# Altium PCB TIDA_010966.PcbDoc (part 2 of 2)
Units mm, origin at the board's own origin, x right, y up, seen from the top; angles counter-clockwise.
Board outline 125.73 x 87.63 mm, 4 copper layers (Top Layer, Layer 1, Layer 2, Bottom Layer), stack 1.047 mm thick; 129 components, 41 nets, 410 pads, 452 vias.
Unrouted connection lines stored in the file: 3.
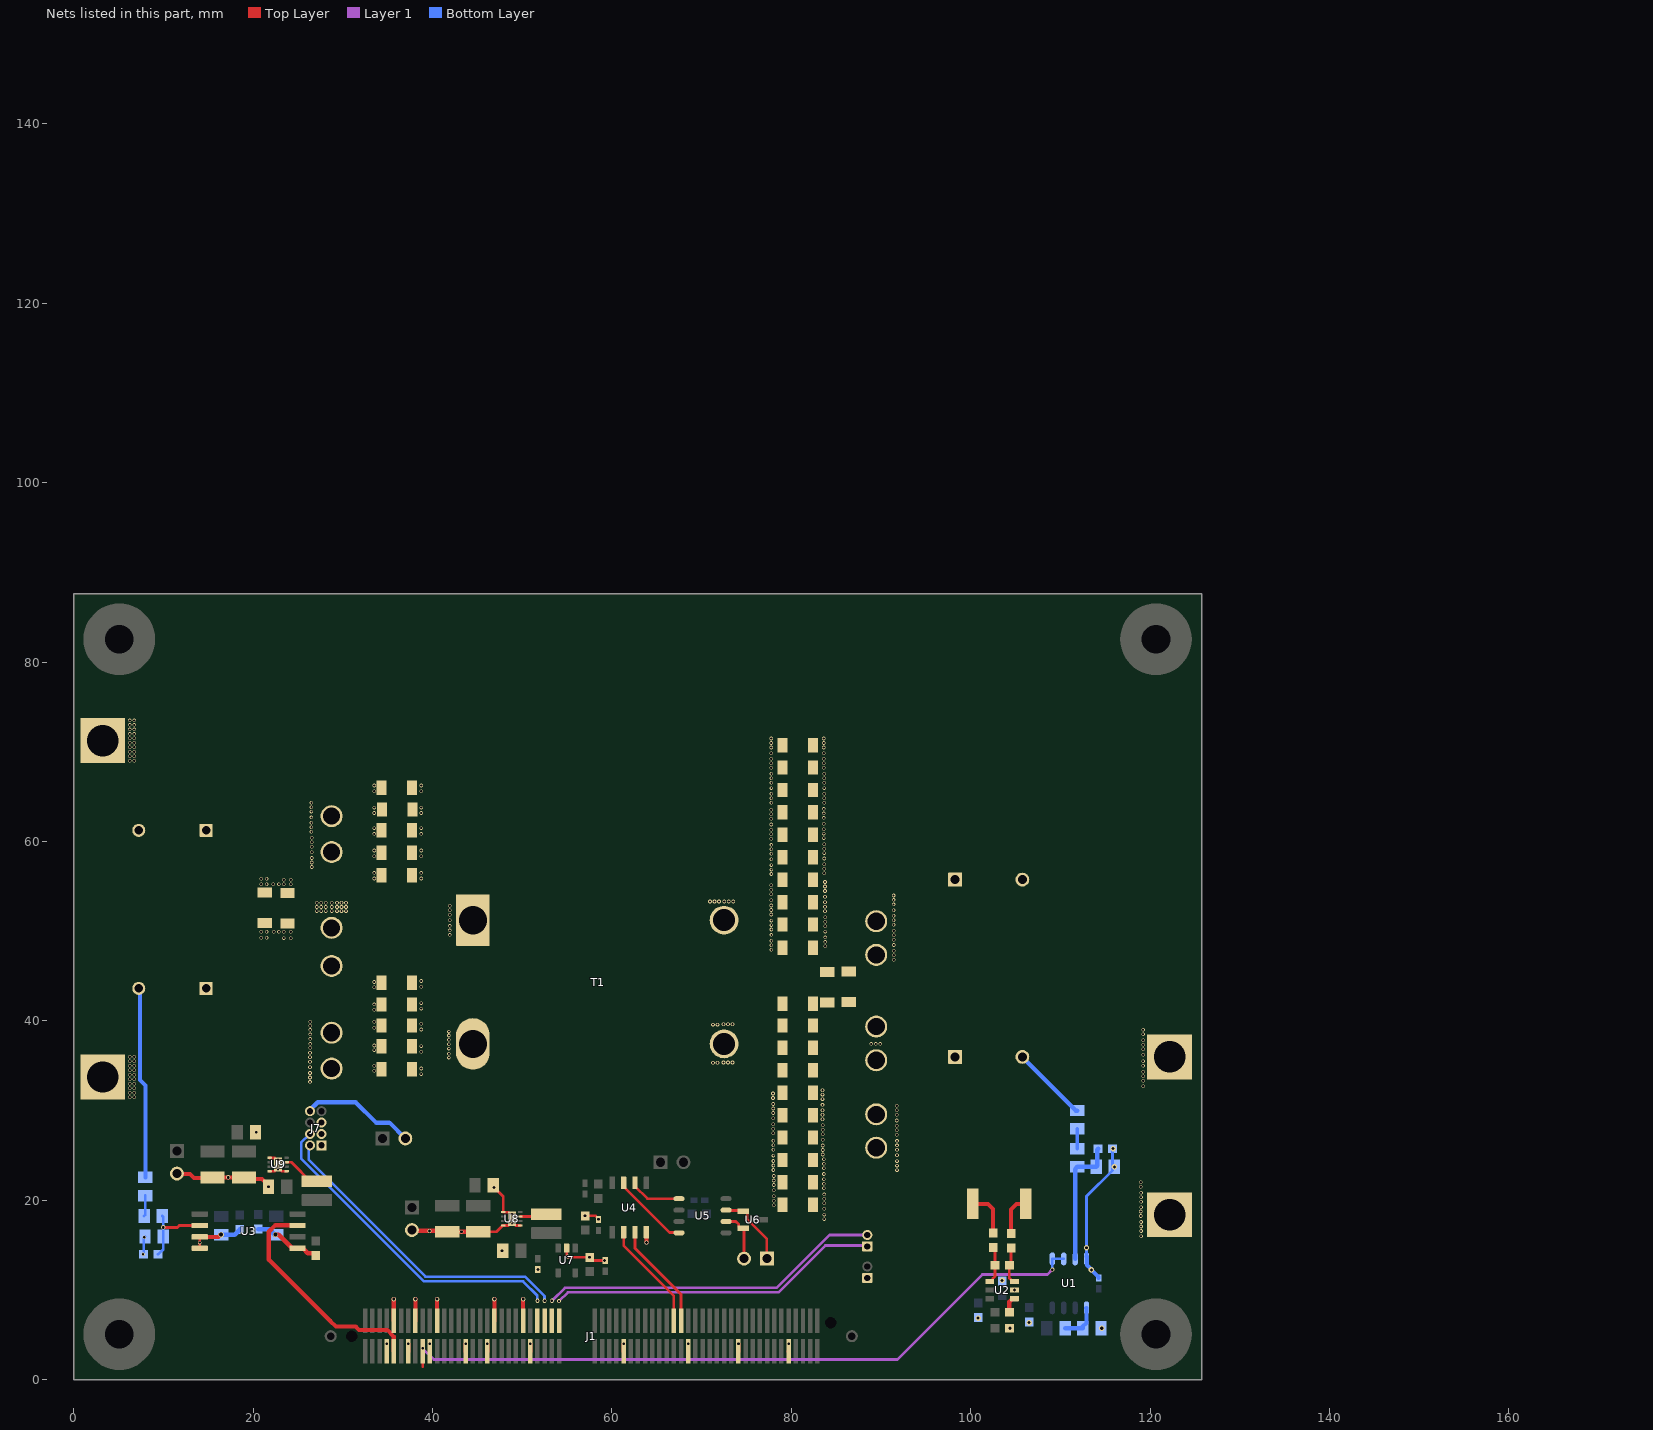
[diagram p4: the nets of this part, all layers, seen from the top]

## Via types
v1: diameter 0.4, hole 0.254, Top Layer to Bottom Layer, tented both sides, 371 vias
v2: diameter 0.5, hole 0.3, Top Layer to Bottom Layer, tented both sides, 31 vias
v3: diameter 0.61, hole 0.35, Top Layer to Bottom Layer, tented both sides, 14 vias
v4: diameter 0.43, hole 0.32, Top Layer to Bottom Layer, tented both sides, 12 vias
v5: diameter 0.45, hole 0.254, Top Layer to Bottom Layer, tented both sides, 5 vias
v6: diameter 0.45, hole 0.26, Top Layer to Bottom Layer, tented both sides, 4 vias
v7: diameter 0.61, hole 0.45, Top Layer to Bottom Layer, tented both sides, 4 vias
v8: diameter 0.5, hole 0.2, Top Layer to Bottom Layer, 4 vias
v9: diameter 0.45, hole 0.33, Top Layer to Bottom Layer, tented both sides, 3 vias
v10: diameter 0.61, hole 0.3, Top Layer to Bottom Layer, tented both sides, 3 vias
v11: diameter 0.45, hole 0.25, Top Layer to Bottom Layer, tented both sides, 1 vias

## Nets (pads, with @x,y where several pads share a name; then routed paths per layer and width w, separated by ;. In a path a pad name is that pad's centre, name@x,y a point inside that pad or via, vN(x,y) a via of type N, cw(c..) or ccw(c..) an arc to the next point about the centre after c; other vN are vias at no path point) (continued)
GND_pri: C5.1 C6.2 C7.2 C8.1 C9.1 C14.2 C15.2 C22.2 C24.2 C26.2 C28.2 C30.2 C64.1 C67.1 C70.2 C74.2 GND_pri2.1 GND_pri.1 J5.2 J7.1 pad.2@3.228,33.75 R11.1 U3.3 U3.4 U9.1 U9.4 U9.5 U9.9@22.78,24 | length 22.7
  Top Layer w0.3: U3.4@14.05,14.659 U3.3@14.05,15.929 ; U9.4@21.83,23.25 22.38,23.25 22.58,23.45 22.98,23.45 23.18,23.25 U9.5@23.73,23.25 ; U9.1@21.83,24.75 21.855,24.725 22.405,24.725 22.58,24.55 v8(22.78,24.55) ; U9.9@22.68,23.55 22.78,23.65 U9.9@22.78,24
  Top Layer w0.45: J5.2@11.5,22.98 11.525,22.955 12.95,22.955 13.416,22.489 15.419,22.489 C67.1@15.48,22.55 v2(17.23,22.55) C64.1@18.98,22.55 19.156,22.374 21.005,22.374 21.714,21.665 v10(21.714,21.5) ; U3.3@14.05,15.929 16.15,15.929 16.389,16.168 v7(16.432,16.168)
  Bottom Layer w0.3: C6.2@7.804,13.995 7.804,15.821 R11.1@7.947,15.964
  Bottom Layer w0.5: v7(16.432,16.168) 17.935,16.168 18.5,16.733 C7.2@18.5,16.758
  other v1: 7.729,13.995 14.05,15.294 7.863,15.88 6.25,31.5 6.75,31.5 6.25,32 6.75,32 6.25,32.5 6.75,32.5 6.25,33 6.75,33 26.34,33.2 6.25,33.5 6.75,33.5 26.34,33.7 6.25,34 6.75,34 26.34,34.2 33.5,34.457 6.25,34.5 6.75,34.5 26.34,34.85 6.25,35 6.75,35 33.5,35 26.34,35.45 6.25,35.5 6.75,35.5 26.34,35.95 6.25,36 6.75,36 26.34,36.45 33.5,36.75 26.357,37 33.5,37.266 26.355,37.439 26.355,38 26.355,38.5 26.355,39 33.5,39.25 26.355,39.459 26.357,39.9 33.5,39.9 33.5,41.25 33.5,41.841 33.5,43.75 33.5,44.339 24.208,49.227 23.427,49.239 21.5,49.275 20.901,49.289 20.901,49.95 21.5,49.95 22.301,49.95 22.877,49.95 23.427,49.95 24.208,49.95
  other v2: 20.35,27.589
  other v8: 22.78,23.45
GND_sec: C1.2 C2.2 C3.2 C10.1 C16.2 C17.1 C18.2 C19.1 C20.2 C31.1 C32.1 C34.2 C36.2 C40.2 C42.2 C44.2 C46.2 C50.2 C52.2 C54.2 C56.2 C57.1 C58.1 C59.2 C62.1 C63.2 C66.1 C68.2 C69.2 C71.2 C72.2 C73.2 GND_sec2.1 GND_sec.1 J1.7 J1.10 J1.13 J1.16 J1.19 J1.22 J1.29 J1.35 J1.38 J1.46 J1.47 J1.65 J1.83 J1.97 J1.111 J4.2 J7.3 J7.5 J9.1 R4.1 R8.1 R10.1 R12.1 U1.4 U2.2 U3.5 U4.4 U7.2 U8.1 U8.4 U8.5 U8.9@48.85,17.952 | length 75.6
  Top Layer w0.3: C62.1@45.1,16.502 47.125,16.502 47.825,17.202 U8.4@47.9,17.202 48.45,17.202 48.65,17.402 v8(48.85,17.402) ; C69.2@46.766,21.702 46.766,21.537 47.9,20.403 U8.1@47.9,18.702 47.925,18.677 48.475,18.677 48.65,18.502 v8(48.85,18.502) ; U8.9@48.85,17.952 48.85,17.602 49.25,17.202 U8.5@49.8,17.202 ; U7.2@54.95,14.677 54.95,13.828 55.126,13.652 v4(57.5,13.652) 57.5,13.627 57.825,13.302 C71.2@59.25,13.302 ; v4(57,18.278) 58.172,18.278 58.5,17.95 C31.1@58.5,17.85
  Top Layer w0.45: J1.7@34.9,3.157 v2(34.9,4) ; v2(35.675,9) 35.675,6.582 J1.10@35.7,6.557 ; J1.13@37.3,3.157 v2(37.3,4) ; J1.16@38.1,6.557 v2(38.1,9) ; J1.19@39.7,3.157 v2(39.7,4) ; J1.22@40.5,6.557 v2(40.5,9) ; J1.29@43.7,3.157 v2(43.7,4) ; J1.35@46.1,3.157 v2(46.1,4) ; J1.38@46.9,6.557 v2(46.9,9) ; J1.46@50.1,6.557 v2(50.1,9) ; J1.47@50.9,3.157 v2(50.9,4) ; J1.65@61.3,3.157 v2(61.3,4) ; v4(63.84,15.303) U4.4@63.84,16.453 ; v2(68.498,4) 68.498,3.159 J1.83@68.5,3.157 ; J1.97@74.1,3.157 v2(74.1,4) ; J1.111@79.7,3.157 79.714,3.171 v2(79.714,4) ; R10.1@100.237,19.6 101.914,19.6 102.494,19.02 R4.1@102.494,16.35
  Top Layer w0.5: v7(22.492,16.183) 22.513,16.162 22.847,16.162 24.35,14.659 U3.5@24.95,14.659 25.55,14.659 26.1,14.109 26.755,14.109 26.98,13.884 C19.1@26.98,13.859 ; J4.2@37.7,16.682 37.79,16.592 41.551,16.592 C66.1@41.641,16.502 C62.1@45.1,16.502
  Bottom Layer w0.3: U1.4@112.905,13.752 112.905,20.458 115.8,23.353 C3.2@115.8,25.766
  Bottom Layer w0.45: U1.4@112.905,13.752 112.934,13.723 112.934,12.766 114.25,11.45 C20.2@114.25,11.35
  Bottom Layer w0.5: C17.1@20.575,16.799 21.794,16.799 22.41,16.183 v7(22.492,16.183) C18.2@22.575,16.183
  other v1: 83.662,17.914 83.662,18.414 83.662,19.064 83.662,19.664 83.662,20.164 83.662,20.664 83.633,21.339 83.633,21.839 83.633,22.339 83.633,22.939 91.779,23.377 83.633,23.589 91.779,23.877 83.633,24.089 91.779,24.377 83.633,24.589 91.779,25.027 83.498,25.114 83.498,25.614 91.779,25.627 83.498,26.114 91.779,26.127 91.779,26.627 83.498,26.764 91.75,27.302 83.498,27.364 91.75,27.802 83.498,27.864 91.75,28.302 83.498,28.364 91.75,28.902 83.469,29.039 83.469,29.539 91.75,29.552 83.469,30.039 91.75,30.052 91.75,30.552 83.469,30.639 83.469,31.289 83.469,31.789 83.469,32.289
  other v3: 104.369,5.75 114.6,5.75 106.511,6.375 100.815,6.877 103.494,11.077 113.45,12.25 116.016,23.734 115.875,25.766
  other v4: 104.869,10 51.75,12.282 59.191,13.302 55.038,13.74 47.75,14.376 43.241,16.502 39.67,16.592 58.5,17.9 46.85,21.453
  other v10: 112.905,14.7
NetC3_1: C3.1 R2.1 R12.2 U1.3 | length 14.6
  Bottom Layer w0.5: U1.3@111.635,13.475 111.635,23.494 R2.1@111.875,23.734 R12.2@113.984,23.734 114.092,23.842 114.092,25.658 C3.1@114.2,25.766
NetC4_1: C4.1 R3.2 U2.3 | length 4.2
  Top Layer w0.3: R3.2@104.494,14.7 104.494,12.95 C4.1@104.294,12.75 104.294,11.325 104.669,10.95 U2.3@104.869,10.95
NetC4_2: C4.2 R4.2 U2.4 | length 4.2
  Top Layer w0.3: U2.4@102.119,10.95 102.319,10.95 102.469,11.1 102.469,11.3 102.694,11.525 C4.2@102.694,12.75 102.694,14.55 R4.2@102.494,14.75
NetC6_1: C6.1 R6.1 R11.2 U3.2 | length 8.7
  Top Layer w0.3: v2(9.979,16.98) 11.545,16.98 11.764,17.199 U3.2@14.05,17.199
  Bottom Layer w0.3: C6.1@9.404,13.995 9.429,13.995 9.979,14.545 R11.2@9.979,15.964 v2(9.979,16.98) 9.979,18.15 R6.1@9.875,18.255
NetC21_2: C21.2 C22.1 C23.2 C24.1 C25.2 C26.1 C27.2 C28.1 C29.2 C30.1 T1.2
  other v1: 38.75,34.079 38.75,34.701 41.827,35.917 41.826,36.355 38.75,36.551 41.826,36.917 38.75,37.201 41.826,37.417 41.826,37.917 41.826,38.376 41.827,38.817 38.75,39.051 38.75,39.701 38.75,41.378 38.75,41.99 38.75,43.801 38.75,44.451 38.75,55.877 38.75,56.5 38.75,58.35 38.75,59 38.75,60.85 38.75,61.5 38.75,63.177 38.75,63.789 38.75,65.6 38.75,66.25
NetC33_2: C33.2 C34.1 C35.2 C36.1 C39.2 C40.1 C41.2 C42.1 C43.2 C44.1 C45.2 C46.1 C49.2 C50.1 C51.2 C52.1 C53.2 C54.1 C55.2 C56.1 T1.4
  other v1: 78.029,19.464 78.029,19.964 78.029,20.464 78.029,21.114 78.029,21.714 78.029,22.214 78.029,22.714 78,23.389 78,23.889 78,24.389 78,24.989 78,25.639 78,26.139 78,26.639 77.988,27.489 77.988,27.989 77.988,28.489 77.988,29.139 77.988,29.739 77.988,30.239 77.988,30.739 77.959,31.414 77.959,31.914 77.779,47.941 77.779,48.441 77.779,48.941 77.779,49.591 77.779,50.191 77.779,50.691 77.779,51.191 77.75,51.866 77.75,52.366 77.75,52.866 70.931,53.321 71.431,53.321 71.931,53.321 72.525,53.321 73.025,53.321 73.525,53.321 77.75,53.466 77.75,54.116 77.75,54.616 77.75,55.116 77.779,56.377 77.779,56.877 77.779,57.377 77.779,58.027 77.779,58.627 77.779,59.127 77.779,59.627 77.75,60.302 77.75,60.802 77.75,61.302 77.75,61.902 77.75,62.552 77.75,63.052 77.75,63.552 77.779,64.314 77.779,64.814 77.779,65.314 77.779,65.964 77.779,66.564 77.779,67.064 77.779,67.564 77.75,68.239 77.75,68.739 77.75,69.239 77.75,69.839 77.75,70.489 77.75,70.989 77.75,71.489
NetJ1_80: J1.80 U4.2 | length 12.2
  Top Layer w0.3: U4.2@61.3,16.453 61.3,14.95 66.9,9.35 J1.80@66.9,6.557
NetJ1_82: J1.82 U4.3 | length 12
  Top Layer w0.3: U4.3@62.57,16.453 62.57,14.66 67.7,9.53 J1.82@67.7,6.557
NetJ3_1: J3.1 U5.7 U6.1 | length 8.5
  Top Layer w0.3: U5.7@72.725,18.913 72.773,18.865 74.584,18.865 U6.1@74.65,18.8 74.949,18.8 75.099,18.65 75.099,17.866 77.27,15.695 J3.1@77.27,13.5
NetJ3_2: J3.2 U5.6 U6.2 | length 5.8
  Top Layer w0.3: U5.6@72.725,17.643 73.8,17.643 74.15,17.293 74.15,17.05 74.3,16.9 U6.2@74.65,16.9 74.73,16.82 J3.2@74.73,13.5
NetL1_1: L1.1 U8.7 | length 3
  Top Layer w0.3: U8.7@49.8,18.202 52.45,18.202 L1.1@52.7,18.452
NetL2_1: L2.1 U9.7 | length 5.9
  Top Layer w0.3: U9.7@23.73,24.25 24.278,24.25 26.58,21.948 L2.1@28.65,21.948
NetR1_1: R1.1 R2.2 | length 2.2
  Bottom Layer w0.381: R2.2@111.875,25.766 R1.1@111.875,27.984
NetR5_1: R5.1 R6.2 | length 2.3
  Bottom Layer w0.3: R6.2@7.843,18.255 7.979,18.391 R5.1@7.979,20.532
NetR7_1: R7.1 R8.2 U1.5 | length 4.5
  Bottom Layer w0.45: R8.2@112.484,5.75 112.484,5.915 112.905,6.336 U1.5@112.905,8.025 U1.5@112.876,7.996
  Bottom Layer w0.5: R7.1@110.516,5.75 R8.2@112.484,5.75
NetR9_1: R9.1 U2.1 | length 1.9
  Top Layer w0.5: R9.1@104.294,7.5 104.294,8.675 104.669,9.05 U2.1@104.869,9.05
NetU4_6: U4.6 U5.1 | length 5.9
  Top Layer w0.3: U4.6@62.57,21.953 62.57,21.553 63.94,20.183 U5.1@67.475,20.183
NetU4_7: U4.7 U5.4 | length 8.7
  Top Layer w0.3: U4.7@61.3,21.953 61.3,21.553 66.432,16.421 67.427,16.421 U5.4@67.475,16.373
Q1_G: J1.50 J7.4 | length 36.4
  Layer 1 w0.3: J7.4@26.332,27.402 J7.4@26.349,27.402 ; v6@51.671,8.836 v6(51.7,8.807)
  Bottom Layer w0.3: J7.4@26.332,27.402 25.359,26.429 25.359,24.657 39.039,10.977 50.1,10.977 51.671,9.406 v6@51.671,8.836
Q2_G: J1.52 J7.2 | length 34.8
  Layer 1 w0.3: J7.2@26.192,25.976 J7.2@26.349,26.132 ; v6@52.471,8.836 v6(52.5,8.807)
  Bottom Layer w0.3: J7.2@26.192,25.976 26.192,24.531 39.223,11.5 50.284,11.5 52.471,9.313 v6@52.471,8.836
Q3_G: J1.54 J8.2 | length 38.2
  Layer 1 w0.3: v6(53.3,8.807) 54.743,10.25 78.36,10.25 84.247,16.137 J8.2@88.464,16.137
Q4_G: J1.56 J8.1 | length 37
  Layer 1 w0.3: v6(54.1,8.765) 55.085,9.75 78.567,9.75 83.784,14.966 88.365,14.966 J8.1@88.464,14.867
SW_pri: J6.2 J7.8 SW_pri2.1 SW_pri.1 T1.1 | length 12.8
  Bottom Layer w0.5: J7.8@26.349,29.942 26.349,30.101 27.201,30.952 31.42,30.952 33.7,28.672 35.2,28.672 J6.2@36.97,26.903
  other v1: 41.933,49.591 41.933,50.091 41.933,50.591 41.933,51.241 41.933,51.841 27.101,52.25 27.601,52.25 28.101,52.25 28.751,52.25 29.351,52.25 29.851,52.25 30.351,52.25 41.933,52.341 27.101,52.7 27.601,52.7 28.101,52.7 28.751,52.7 29.351,52.7 29.851,52.7 30.351,52.7 41.933,52.841 27.101,53.165 27.601,53.165 28.101,53.165 28.751,53.165 29.351,53.165 29.851,53.165 30.351,53.165
SW_sec: SW_sec2.1 SW_sec.1 T1.3
  other v1: 71.265,35.34 71.765,35.34 72.44,35.369 72.94,35.369 73.44,35.369 88.92,37.439 89.42,37.439 89.92,37.439 71.265,39.598 71.765,39.598 72.44,39.627 72.94,39.627 73.44,39.627
Vbattery_n: pad.2@122.174,18.4 R3.1 R10.2 | length 4.6
  Top Layer w0.45: R3.1@104.494,16.3 104.494,18.987 105.108,19.6 R10.2@106.137,19.6
  other v1: 118.988,15.985 118.988,16.585 118.988,17.085 118.988,17.585 118.959,18.26 118.959,18.76 118.988,19.235 118.988,19.835 118.988,20.335 118.988,20.835 118.959,21.51 118.959,22.01
Vbattery_p: C33.1 C35.1 C39.1 C41.1 C43.1 C45.1 C49.1 C51.1 C53.1 C55.1 C57.2 C58.2 C59.1 C68.1 pad.2@122.174,36 R1.2 Vbattery_p2.1 Vbattery_p.1 | length 8.6
  Bottom Layer w0.5: C58.2@105.75,36 105.75,35.976 111.71,30.016 R1.2@111.875,30.016
  other v1: 119.238,32.735 119.238,33.335 119.238,33.835 119.238,34.335 119.209,35.01 119.209,35.51 119.238,36.235 119.238,36.835 119.238,37.335 119.238,37.835 119.209,38.51 119.209,39.01 91.429,46.814 91.429,47.314 91.429,47.814 83.779,48.314 91.429,48.464 83.779,48.814 91.429,49.064 83.779,49.314 91.429,49.564 83.779,49.964 91.429,50.064 83.779,50.564 91.4,50.739 83.779,51.064 91.4,51.239 83.779,51.564 91.4,51.739 83.75,52.239 91.4,52.339 83.75,52.739 91.4,52.989 83.75,53.239 91.4,53.489 83.75,53.839 91.4,53.989 83.75,54.489 83.75,54.989 83.75,55.489 83.654,56.461 83.654,56.961 83.654,57.461 83.654,58.111 83.654,58.711 83.654,59.211 83.654,59.711 83.625,60.386 83.625,60.886 83.625,61.386 83.625,61.986 83.625,62.636 83.625,63.136 83.625,63.636 83.654,64.314 83.654,64.814 83.654,65.314 83.654,65.964 83.654,66.564 83.654,67.064 83.654,67.564 83.625,68.239 83.625,68.739 83.625,69.239 83.625,69.839 83.625,70.489 83.625,70.989 83.625,71.489
Vbattery_sen: J1.17 U1.1 U1.2 | length 79
  Top Layer w0.3: 38.9,1.452 J1.17@38.9,3.157
  Layer 1 w0.3: v5(38.9,3.5) 40.143,2.257 91.821,2.257 101.296,11.732 108.544,11.732 v11(109.088,12.275)
  Bottom Layer w0.3: v11(109.088,12.275) 109.095,12.282 U1.1@109.095,13.475 U1.2@110.365,13.475
Vbus_p: C5.2 C9.2 C14.1 C15.1 C21.1 C23.1 C25.1 C27.1 C29.1 pad.2@3.228,71.25 R5.2 Vbus_p2.1 Vbus_p.1 | length 21.4
  Bottom Layer w0.45: C9.2@7.25,43.627 7.375,43.502 7.375,33.405 7.979,32.801 R5.2@7.979,22.564
  other v1: 20.901,55.25 21.5,55.25 22.228,55.25 22.877,55.25 23.427,55.25 24.208,55.25 23.427,55.734 24.2,55.734 20.901,55.85 21.5,55.85 33.5,55.877 33.5,56.5 26.529,57.164 26.529,57.664 26.529,58.164 33.5,58.35 26.529,58.814 33.5,59 26.529,59.414 26.529,59.914 26.529,60.414 33.5,60.85 26.5,61.089 33.5,61.5 26.5,61.589 26.5,62.089 26.5,62.689 33.5,63.177 26.5,63.339 33.5,63.789 26.5,63.839 26.5,64.339 33.5,65.6 33.5,66.25 6.25,69 6.75,69 6.25,69.5 6.75,69.5 6.25,70 6.75,70 6.25,70.5 6.75,70.5 6.25,71 6.75,71 6.25,71.5 6.75,71.5 6.25,72 6.75,72 6.25,72.5 6.75,72.5 6.25,73 6.75,73 6.25,73.5 6.75,73.5
Vbus_sense: J1.9 U3.7 | length 25.8
  Top Layer w0.45: 28.58,6.557 29.22,5.917 31.439,5.917 31.824,5.532 34.968,5.532 35.675,4.825 35.675,3.182 J1.9@35.7,3.157
  Top Layer w0.5: U3.7@24.95,17.199 22.441,17.199 21.738,16.496 21.738,13.4 28.58,6.557
pads on no net: H1.1 H2.1 H3.1 H4.1 H5.0 H6.0 H7.0 H8.0 H9.0 H10.0 H11.0 H12.0 J1.1 J1.2 J1.3 J1.4 J1.5 J1.6 J1.8 J1.12 J1.14 J1.18 J1.20 J1.21 J1.23 J1.24 J1.25 J1.26 J1.27 J1.28 J1.30 J1.31 J1.32 J1.33 J1.34 J1.36 J1.37 J1.39 J1.40 J1.41 J1.42 J1.43 J1.44 J1.45 J1.49 J1.51 J1.53 J1.55 J1.57 J1.58 J1.59 J1.60 J1.61 J1.62 J1.63 J1.64 J1.66 J1.67 J1.68 J1.69 J1.70 J1.71 J1.72 J1.73 J1.74 J1.75 J1.76 J1.77 J1.78 J1.79 J1.81 J1.85 J1.86 J1.87 J1.88 J1.89 J1.90 J1.91 J1.92 J1.93 J1.94 J1.95 J1.96 J1.99 J1.100 J1.101 J1.102 J1.103 J1.104 J1.105 J1.106 J1.107 J1.108 J1.109 J1.110 J1.113 J1.114 J1.115 J1.116 J1.117 J1.118 J1.119 J1.120 J1.181 J1.182 J1.185 J1.186 U5.5 U7.4 U8.8 U8.9@48.85,17.502 U8.9@48.85,18.402 U9.8 U9.9@22.78,23.55 U9.9@22.78,24.45

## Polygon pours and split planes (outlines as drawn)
NetC33_2 on Top Layer "TOP_LAYER_NETC33_2_P020" (solid, remove dead copper, pour order 20): 72,76.5 70.25,74.75 70.25,49.795 76.241,43.804 76.241,20.407 77.924,18.723 79.197,18.723 80,19.527 80,75.5 79,76.5
Vbattery_p on Top Layer "TOP_LAYER_VBATTERY_P_P021" (solid, remove dead copper, pour order 21): 84,76.5 82,74.5 82,46.25 83.407,44.843 90.168,44.843 91.939,46.615 91.939,68.25 102.75,68.25 104,67 104,33.8 106.3,31.5 111.25,31.5 112.5,32.75 112.5,74.25 110.25,76.5
GND_sec on Top Layer "TOP_LAYER_GND_SEC_P005" (solid, remove dead copper, pour order 5): 100.15,59 100.75,58.4 100.75,18.75 99.25,17.25 83.864,17.25 82.114,19 82.114,42.614 82.5,43 91,43 94.687,46.687 94.687,58.418 95.269,59
NetC21_2 on Top Layer "TOP_LAYER_NETC21_2_P017" (solid, remove dead copper, pour order 17): 37.5,74.5 37,74 37,32.792 38.864,30.927 47.364,30.927 48.76,32.323 48.76,39.834 46.664,41.929 42.871,41.929 41.5,43.3 41.5,74.075 41.075,74.5
Vbattery_p on Top Layer "TOP_LAYER_VBATTERY_P_P009" (solid, remove dead copper, pour order 9): 107.107,39.25 106.459,38.308 106.459,32.352 107.311,31.5 124.455,31.5 125.083,32.128 125.083,38.575 124.504,39.25
Vbattery_n on Top Layer "TOP_LAYER_VBATTERY_N_P008" (solid, remove dead copper, pour order 8): 106.511,22.718 105.914,21.849 105.914,16.327 106.766,15.475 124.705,15.475 125.175,15.945 125.175,22.054 124.606,22.718
GND_pri on Top Layer "TOP_LAYER_GND_PRI_P007" (solid, remove dead copper, pour order 7): 0.647,36.66 0.647,31 15,31 15,34 12.34,36.66
GND_pri on Top Layer "TOP_LAYER_GND_PRI_P001" (solid, remove dead copper, pour order 1): 12.491,64.069 11.916,63.494 11.916,34 14.916,31 33.333,31 35.148,32.815 35.148,49.95 34.098,51 18.615,51 17.25,52.365 17.25,63.5 16.681,64.069
Vbus_p on Top Layer "TOP_LAYER_VBUS_P_P000" (solid, remove dead copper, pour order 0): 9,40.75 8,39.75 2,39.75 0.647,41.103 0.647,73.897 1.25,74.5 33.01,74.5 35.25,72.26 35.25,55.877 33.623,54.25 20.351,54.25 20.351,66.25 19.351,67.25 11,67.25 9,65.25
SW_sec on Layer 2 "LAYER_2_SW_SEC_P025" (solid, remove dead copper, pour order 25): 72.229,43.5 70.3,41.571 70.3,34.824 72.474,32.65 92.425,32.65 93.285,33.51 93.285,41.268 91.053,43.5
SW_pri on Layer 2 "LAYER_2_SW_PRI_P016" (solid, remove dead copper, pour order 16): 27.637,55.066 26.085,53.515 26.085,45.926 27.673,44.339 31.472,44.339 34.415,47.281 46.53,47.281 48,48.752 48,53.25 46.25,55
GND_sec on Layer 2 "LAYER_2_GND_SEC_P013" (solid, remove dead copper, pour order 13): 71.588,29.25 24.73,29.25 19.429,23.949 19.429,3.106 21.559,0.976 115.64,0.976 117.654,2.99 117.654,27.196 115.85,29 108.137,29 105.542,26.405 105.542,17.718 104.847,17.024 76.379,17.024 75.5,17.902 75.5,25.338
NetC33_2 on Layer 1 "LAYER_1_NETC33_2_P019" (solid, remove dead copper, pour order 19): 72,76.5 70.25,74.75 70.25,49.795 76.241,43.804 76.241,20.407 77.924,18.723 79.197,18.723 80,19.527 80,75.5 79,76.5
Vbattery_n on Layer 1 "LAYER_1_VBATTERY_N_P026" (solid, remove dead copper, pour order 26): 106.511,22.718 105.914,21.849 105.914,16.327 106.766,15.475 124.705,15.475 125.175,15.945 125.175,22.054 124.606,22.718
GND_sec on Layer 1 "LAYER_1_GND_SEC_P023" (solid, remove dead copper, pour order 23): 100.15,59 100.75,58.4 100.75,18.75 99.25,17.25 83.864,17.25 82.114,19 82.114,42.614 82.5,43 91,43 94.687,46.687 94.687,58.418 95.269,59
Vbattery_p on Layer 1 "LAYER_1_VBATTERY_P_P022" (solid, remove dead copper, pour order 22): 107.107,39.25 106.459,38.308 106.459,32.352 107.311,31.5 124.455,31.5 125.083,32.128 125.083,38.575 124.504,39.25
Vbattery_p on Layer 1 "LAYER_1_VBATTERY_P_P004" (solid, remove dead copper, pour order 4): 84,76.5 82,74.5 82,46.25 83.407,44.843 90.168,44.843 91.939,46.615 91.939,68.25 102.75,68.25 104,67 104,33.8 106.3,31.5 111.25,31.5 112.5,32.75 112.5,74.25 110.25,76.5
NetC21_2 on Layer 1 "LAYER_1_NETC21_2_P018" (solid, remove dead copper, pour order 18): 37.5,74.5 37,74 37,32.792 38.864,30.927 47.364,30.927 48.76,32.323 48.76,39.834 46.664,41.929 42.871,41.929 41.5,43.3 41.5,74.075 41.075,74.5
GND_pri on Layer 1 "LAYER_1_GND_PRI_P006" (solid, remove dead copper, pour order 6): 0.647,36.66 0.647,31 15,31 15,34 12.34,36.66
GND_pri on Layer 1 "LAYER_1_GND_PRI_P003" (solid, remove dead copper, pour order 3): 12.491,64.069 11.916,63.494 11.916,34 14.916,31 33.333,31 35.148,32.815 35.148,49.95 34.098,51 18.615,51 17.25,52.365 17.25,63.5 16.681,64.069
Vbus_p on Layer 1 "LAYER_1_VBUS_P_P002" (solid, remove dead copper, pour order 2): 9,40.75 8,39.75 2,39.75 0.647,41.103 0.647,73.897 1.25,74.5 33.01,74.5 35.25,72.26 35.25,55.877 33.623,54.25 20.351,54.25 20.351,66.25 19.351,67.25 11,67.25 9,65.25
GND_pri on Layer 1 "LAYER_1_GND_PRI_P011" (solid, remove dead copper, pour order 11): 7.251,28.192 5.849,26.79 5.849,13.15 7.499,11.5 27,11.5 28.65,13.15 28.65,27.273 27.581,28.192
GND_ISO on Layer 1 "LAYER_1_GND_ISO_P010" (solid, remove dead copper, pour order 10): 59.23,25.75 58.75,25.27 58.75,18.8 59.425,18.125 74.574,18.125 75.5,19.051 75.5,25.25 75,25.75
SW_sec on Bottom Layer "BOTTOM_LAYER_SW_SEC_P024" (solid, remove dead copper, pour order 24): 72.229,43.5 70.3,41.571 70.3,34.824 72.474,32.65 92.425,32.65 93.285,33.51 93.285,41.268 91.053,43.5
SW_pri on Bottom Layer "BOTTOM_LAYER_SW_PRI_P015" (solid, remove dead copper, pour order 15): 27.637,55.066 26.085,53.515 26.085,45.926 27.673,44.339 31.472,44.339 34.415,47.281 46.53,47.281 48,48.752 48,53.25 46.25,55
5V_sec on Bottom Layer "BOTTOM_LAYER_5V_SEC_P012" (solid, remove dead copper, pour order 12): 50.241,17.643 49.3,16.702 49.3,7.7 50.25,6.75 81.614,6.75 82.5,7.636 82.5,10.95 82.45,10.95 81.323,12.077 60.725,12.077 60.22,12.582 60.22,17.265 59.842,17.643

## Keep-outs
Keep-Out Layer:
  text ".Layer_Name" at 14.656,-21.806 h0.35

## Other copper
Top Layer:
  text ".Layer_Name" at 14.656,-21.806 h0.35
Bottom Layer:
  text ".Layer_Name" at 14.656,-21.806 h0.35

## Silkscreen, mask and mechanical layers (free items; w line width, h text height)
Top Overlay:
  text "TIDA-010966" at 44.15,82.745 h0.95
  text ".Layer_Name" at 14.656,-21.806 h0.35
Bottom Overlay:
  text ".Layer_Name" at 14.656,-21.806 h0.35
Top Paste:
  text ".Layer_Name" at 14.656,-21.806 h0.35
Bottom Paste:
  text ".Layer_Name" at 14.656,-21.806 h0.35
Top Solder:
  text ".Layer_Name" at 14.656,-21.806 h0.35
  text ".Layer_Name" at 14.656,-21.806 h0.35
Bottom Solder:
  text ".Layer_Name" at 14.656,-21.806 h0.35
Drill Guide:
  text ".Layer_Name" at 14.656,-21.806 h0.35
M1 Board Outline:
  the board outline again, w0.254
  text ".Layer_Name" at 14.656,-21.806 h0.35
M2 Board Dimensions:
  rectangle: 0,-6.985 3.175,-3.81
  rectangle: 3.175,-10.16 12.7,-6.985
  lines w0.178: 0,-6.985 25.4,-6.985 ; 3.175,-10.16 3.175,-3.81 ; 6.35,-10.16 6.35,-3.81 ; 12.7,-10.16 12.7,-3.81 ; 19.05,-10.16 19.05,-3.81 ; 0,-10.16 25.4,-10.16 25.4,-3.81 0,-3.81 0,-10.16
  text ".Layer_Name" at 14.656,-21.806 h0.35
M3 3D STEP Top:
  text ".Layer_Name" at 14.656,-21.806 h0.35
M4 3D STEP Bottom:
  text ".Layer_Name" at 14.656,-21.806 h0.35
M5 Assembly Top:
  lines w0.254: -7.417,-23.626 160.223,-23.626 ; -7.417,-18.462 160.274,-18.462 ; -7.417,-13.297 -7.417,-28.791 94.31,-28.791 160.274,-28.791 160.274,-13.297 -7.404,-13.297 -7.404,-28.791 32.614,-28.791 ; 55.194,-28.791 55.194,-13.297 ; 87.376,-18.462 87.376,-13.297 ; 108.712,-18.462 108.712,-13.297 ; 124.511,-28.956 124.511,-23.804
  text "COMPONENTS MARKED 'DNP' SHOULD NOT BE POPULATED." at 29.299,-8.09 h0.35
  text "ASSEMBLY VARIANT:" at 29.286,-11.024 h0.35
  text ".VariantName" at 55.601,-11.024 h0.35
  text "PCB VIEWED FROM TOP SIDE" at -5.804,-16.654 h0.35
  text "BOARD #:" at 57.099,-16.654 h0.35
  text ".PRJ_Number" at 70.955,-16.654 h0.35
  text "REV:" at 92.405,-16.654 h0.35
  text ".PCB_Rev" at 99.809,-16.654 h0.35
  text "SVN REV:" at 113.69,-16.654 h0.35
  text ".VersionControl_RevNumber" at 126.543,-16.654 h0.35
  text "TID #:" at 57.099,-21.819 h0.35
  text ".TID" at 70.955,-21.819 h0.35
  text "PLOT NAME =" at -5.804,-27.034 h0.35
  text ".plot_File_Name" at 14.656,-27.034 h0.35
  text "GENERATED    :" at 57.15,-27.034 h0.35
  text ".Print_Date" at 79.235,-27.034 h0.35
  text ".Print_Time" at 97.752,-27.034 h0.35
  text "TEXAS INSTRUMENTS" at 129.87,-27.034 h0.35
M6 Assembly Bottom:
  lines w0.254: -7.429,-18.474 160.261,-18.474 ; -7.379,-23.639 160.261,-23.639 ; 28.334,-28.969 28.334,-23.817 ; 44.133,-18.474 44.133,-13.31 ; 65.468,-18.474 65.468,-13.31 ; 97.65,-28.804 97.65,-13.31 ; 120.231,-28.804 160.249,-28.804 160.249,-13.31 -7.429,-13.31 -7.429,-28.804 58.534,-28.804 160.261,-28.804 160.261,-13.31
  text "COMPONENTS MARKED 'DNP' SHOULD NOT BE POPULATED." at 154.991,-8.077 h0.35
  text ".VariantName" at 128.473,-11.024 h0.35
  text "ASSEMBLY VARIANT:" at 154.864,-11.024 h0.35
  text ".VersionControl_RevNumber" at 26.302,-16.667 h0.35
  text "SVN REV:" at 39.154,-16.667 h0.35
  text ".PCB_Rev" at 53.035,-16.667 h0.35
  text "REV:" at 60.439,-16.667 h0.35
  text ".PRJ_Number" at 81.89,-16.667 h0.35
  text "BOARD #:" at 95.745,-16.667 h0.35
  text "PCB VIEWED FROM BOTTOM SIDE" at 158.648,-16.667 h0.35
  text ".TID" at 81.89,-21.831 h0.35
  text "TID #:" at 95.745,-21.831 h0.35
  text "TEXAS INSTRUMENTS" at 22.974,-27.047 h0.35
  text ".Print_Time" at 55.093,-27.047 h0.35
  text ".Print_Date" at 73.609,-27.047 h0.35
  text "GENERATED    :" at 95.694,-27.047 h0.35
  text ".plot_File_Name" at 138.189,-27.047 h0.35
  text "PLOT NAME =" at 158.648,-27.047 h0.35
M9 Title Sheet:
  drawing of 57 lines, arcs and shapes, not listed
  text "1" at 18.792,204.127 h0.35
  text "2" at 82.182,204.127 h0.35
  text "3" at 145.411,204.127 h0.35
  text "4" at 209.08,204.127 h0.35
  text "5" at 272.555,204.127 h0.35
  text "6" at 336.182,204.127 h0.35
  text "A" at -10.579,175.095 h0.35
  text "A" at 365.341,175.095 h0.35
  text "B" at -10.579,114.643 h0.35
  text "B" at 365.341,114.643 h0.35
  text "C" at -10.579,54.318 h0.35
  text "C" at 365.341,54.318 h0.35
  text "PROJECT TITLE:" at 288.125,7.048 h0.35
  text ".PRJ_Title" at 289.395,3.662 h0.35
  text "DESIGNED FOR:" at 288.125,-0.597 h0.35
  text ".PRJ_Customer" at 289.395,-4.153 h0.35
  text "D" at -10.579,-5.88 h0.35
  text "D" at 365.341,-5.88 h0.35
  text "FILE NAME:" at 288.125,-8.217 h0.35
  text ".PCB_File_Name_No_Path" at 289.395,-11.265 h0.35
  text "Texas Instruments (TI) and/or its licensors do not warrant the accuracy or completeness of this specification" at 161.9,-15.376 h0.35
  text "ENGINEER:" at 288.125,-15.583 h0.35
  text "LAYOUT BY:" at 326.352,-15.583 h0.35
  text "or any information contained therein. TI and/or its licensors do not warrant that this design will meet" at 160.757,-18.237 h0.35
  text ".PRJ_Engineer" at 289.395,-19.52 h0.35
  text ".PCB_Layout" at 327.635,-19.52 h0.35
  text "the specifications, will be suitable for your application or fit for any particular purpose, or will operate in" at 160.757,-21.099 h0.35
  text ".Layer_Name" at 14.656,-21.806 h0.35
  text "ALTIUM DESIGNER VERSION:" at 326.352,-23.457 h0.35
  text "an implementation. TI and/or its licensors do not warrant that the design is production worthy. You should" at 160.757,-23.961 h0.35
  text "completely validate and test your design implementation to confirm the system functionality for your application." at 161.9,-26.822 h0.35
  text ".print_Scale" at 289.395,-26.843 h0.35
  text ".Application_BuildNumber" at 327.635,-26.843 h0.35
  text "1" at 18.792,-32.093 h0.35
  text "2" at 82.182,-32.093 h0.35
  text "3" at 145.411,-32.093 h0.35
  text "4" at 209.08,-32.093 h0.35
  text "5" at 272.555,-32.093 h0.35
  text "6" at 336.182,-32.093 h0.35
M10 Fab Notes:
  drawing of 189 lines, arcs and shapes, not listed
  text "DESIGN INFORMATION" at 314.503,161.447 h0.35
  text "MIN. TRACK WIDTH:" at 298.131,158.091 h0.35
  text "8" at 325.976,158.091 h0.35
  text "MIL" at 329.907,158.091 h0.35
  text "7.874" at 321.75,155 h0.35
  text "MIN. CLEARANCE:" at 298.131,154.938 h0.35
  text "MIL" at 329.907,154.938 h0.35
  text "MIN. VIA PAD SIZE:" at 298.131,151.785 h0.35
  text "24" at 325.214,151.785 h0.35
  text "MIL" at 329.907,151.785 h0.35
  text "0.05mm (2MIL)" at 315.784,148.486 h0.35
  text "MINIMUM ANNULAR RING" at 289.769,148.277 h0.35
  text "EXTERNAL" at 333.768,148.277 h0.35
  text "PER" at 294.849,145.48 h0.35
  text "IPC-D-275 CLASS 2 LEVEL C" at 300.437,145.48 h0.35
  text "MIL, HOLES" at 338.238,142.928 h0.35
  text "+/-" at 328.27,142.709 h0.35
  text "+/-" at 349.961,142.709 h0.35
  text "REGISTRATION TOLERANCES:" at 289.769,142.682 h0.35
  text "METAL" at 320.243,142.682 h0.35
  text "5" at 334.879,142.683 h0.35
  text "3" at 356.037,142.683 h0.35
  text "MIL" at 358.99,142.682 h0.35
  text "HOLE SIZE TOLERANCE (UNLESS OTHERWISE SPECIFIED):" at 289.769,140.185 h0.35
  text "+/-" at 349.961,140.112 h0.35
  text "3" at 356.037,140.085 h0.35
  text "MIL" at 358.99,140.085 h0.35
  text "MATERIAL:" at 287.87,136.589 h0.35
  text "FR-4 High Tg" at 312.926,133.324 h0.35
  text "X" at 309.257,133.122 h0.35
  text "FR-4" at 298.563,133.007 h0.35
  text "OTHER" at 336.358,133.007 h0.35
  text "62 MIL (1.6mm) +/-10%" at 306.694,129.374 h0.35
  text "X" at 303.643,129.312 h0.35
  text "THICKNESS:" at 289.769,129.165 h0.35
  text "OTHER" at 339.33,129.165 h0.35
  text "TOLERANCE:" at 289.769,125.652 h0.35
  text "X" at 311.314,125.652 h0.35
  text "ANSI IPC-6012 TYPE 3 CLASS 2" at 315.836,125.652 h0.35
  text "OTHER +/-" at 315.835,121.989 h0.35
  text "BOW & TWIST:" at 289.769,118.302 h0.35
  text "X" at 311.314,118.302 h0.35
  text "ANSI IPC-6012 TYPE 3 CLASS 2" at 315.836,118.302 h0.35
  text "OTHER +/-" at 315.835,114.576 h0.35
  text "DRILLING:" at 287.87,111.258 h0.35
  text "NC_DRILL FILES" at 332.599,108.586 h0.35
  text "REFERENCE:" at 289.769,108.486 h0.35
  text "X" at 306.463,108.484 h0.35
  text "AS SHOWN" at 310.984,108.486 h0.35
  text "X" at 329.348,108.486 h0.35
  text "OTHER" at 340.168,104.873 h0.35
  text "PTH COPPER THICKNESS:" at 289.761,104.783 h0.35
  text "X" at 318.697,104.783 h0.35
  text "20-30 um" at 321.948,104.783 h0.35
  text "BOARD FINISH:" at 287.87,101.034 h0.35
  text "SILKSCREEN:" at 291.812,98.237 h0.35
  text "X" at 316.14,98.237 h0.35
  text "TOP" at 319.112,98.237 h0.35
  text "X" at 329.094,98.237 h0.35
  text "BOTTOM" at 332.091,98.237 h0.35
  text "SILKSCREEN COLOR:" at 291.812,94.295 h0.35
  text "X" at 316.115,94.295 h0.35
  text "WHITE" at 319.112,94.295 h0.35
  text "OTHER" at 332.091,94.295 h0.35
  text "X" at 319.442,90.652 h0.35
  text "GREEN" at 322.439,90.652 h0.35
  text "OTHER" at 338.136,90.652 h0.35
  text "SOLDER RESIST COLOR:" at 291.812,90.477 h0.35
  text "X" at 319.442,86.734 h0.35
  text "MATTE" at 322.439,86.734 h0.35
  text "SEMI-GLOSS" at 338.125,86.717 h0.35
  text "IMMERSION GOLD (ENIG)" at 314.819,82.345 h0.35
  text "ENEPIG" at 348.793,82.162 h0.35
  text "SURFACE FINISH:" at 287.87,82.136 h0.35
  text "X" at 310.298,82.136 h0.35
  text "IMM. TIN/SILVER OR EQUIV" at 296.24,78.649 h0.35
  text "OTHER" at 332.599,78.549 h0.35
  text "ARRAY/PANEL:" at 287.87,74.602 h0.35
  text "CUT AND TRIM PER M1 BOARD OUTLINE" at 314.819,74.393 h0.35
  text "N.C. ROUTE" at 314.819,70.94 h0.35
  text "X" at 332.295,70.94 h0.35
  text "V. SCORE" at 336.816,70.94 h0.35
  text "CERTIFICATION:" at 287.87,67.66 h0.35
  text "MATERIALS AND WORKMANSHIP FOR ALL PCBS" at 306.285,67.66 h0.35
  text "TO MEET OR EXCEED THE REQUIREMENTS OF:" at 306.285,65.271 h0.35
  text "X" at 297.078,62.003 h0.35
  text "ANSI IPC-A-600F CLASS ->" at 300.329,62.003 h0.35
  text "X" at 342.188,62.003 h0.35
  text "2" at 344.982,62.003 h0.35
  text "1" at 336.981,61.965 h0.35
  text "3" at 353.973,61.965 h0.35
  text "X" at 317.702,58.252 h0.35
  text "RoHS" at 320.953,58.252 h0.35
  text "OTHER" at 337.321,58.252 h0.35
  text "PER ORDER" at 347.407,58.252 h0.35
  text "ALL BOARDS MUST MEET OR EXCEED UL94-V0 REQUIREMENTS." at 288.569,54.345 h0.35
  text "PCB MUST BEAR THE UL94V-0 UL REGISTERED MATERIAL ID NUMBER" at 288.569,51.397 h0.35
  text "ADDITIONAL REQUIREMENTS:" at 287.87,47.094 h0.35
  text "MICROSECTION:" at 289.769,44.373 h0.35
  text "YES" at 312.775,44.373 h0.35
  text "REQUIRED" at 334.657,40.707 h0.35
  text "BARE BOARD ELEC. TEST:" at 289.769,40.634 h0.35
  text "NONE" at 322.935,40.634 h0.35
  text "X" at 331.66,40.634 h0.35
  text "PER ORDER" at 349.693,40.634 h0.35
  text "XX MIL VIAS REQUIRE NON-CONDUCTIVE FILL AND PLANARIZE" at 294.04,35.428 h0.35
  text "XX MIL VIAS REQUIRE CONDUCTIVE FILL AND PLANARIZE" at 294.243,32.787 h0.35
  text "OUTER XX MIL TRACES REQUIRE 50 OHM SINGLE-ENDED IMPEDANCE" at 294.218,28.637 h0.35
  text "LAYER 2 & 3 (INNER LAYERS) XX MIL WIDE, XX MIL SPACE / TRACES REQUIRE 100 OHM DIFFERENTIAL IMPEDANCE" at 294.015,22.65 h0.35
  text ".Layer_Name" at 14.656,-21.806 h0.35
M11 Gerber Information:
  lines w0.254: -7.417,-23.626 160.223,-23.626 ; -7.417,-18.462 160.274,-18.462 ; -7.417,-13.297 -7.417,-28.791 94.31,-28.791 160.274,-28.791 160.274,-13.297 -7.404,-13.297 -7.404,-28.791 32.614,-28.791 ; 55.194,-28.791 55.194,-13.297 ; 87.376,-18.462 87.376,-13.297 ; 108.712,-18.462 108.712,-13.297 ; 124.511,-28.956 124.511,-23.804
  text "ALL ARTWORK VIEWED FROM TOP SIDE" at -5.804,-16.654 h0.35
  text "BOARD #:" at 57.099,-16.654 h0.35
  text ".PRJ_Number" at 70.955,-16.654 h0.35
  text "REV:" at 92.405,-16.654 h0.35
  text ".PCB_Rev" at 99.809,-16.654 h0.35
  text "SVN REV:" at 113.69,-16.654 h0.35
  text ".VersionControl_RevNumber" at 126.543,-16.654 h0.35
  text "LAYER NAME =" at -5.804,-21.806 h0.35
  text "TID #:" at 57.099,-21.819 h0.35
  text ".TID" at 70.955,-21.819 h0.35
  text "PLOT NAME =" at -5.804,-27.034 h0.35
  text ".plot_File_Name" at 14.656,-27.034 h0.35
  text "GENERATED    :" at 57.15,-27.034 h0.35
  text ".Print_Date" at 79.235,-27.034 h0.35
  text ".Print_Time" at 97.752,-27.034 h0.35
  text "TEXAS INSTRUMENTS" at 129.87,-27.034 h0.35
M12 Stackup:
  drawing of 196 lines, arcs and shapes, not listed
  text "Layer" at 248.04,201.785 h0.35
  text "Name" at 249.502,201.785 h0.35
  text "Material" at 252.327,201.785 h0.35
  text "Thickness" at 254.866,201.785 h0.35
  text "Constant" at 256.952,201.785 h0.35
  text "Board Layer Stack" at 258.882,201.785 h0.35
  text "Top Overlay" at 249.502,201.085 h0.35
  text "Top Solder" at 249.502,200.385 h0.35
  text "Solder Resist" at 252.327,200.385 h0.35
  text "0.40mil" at 254.866,200.385 h0.35
  text "3.5" at 256.952,200.385 h0.35
  text "1" at 248.04,199.685 h0.35
  text "Top Layer" at 249.502,199.685 h0.35
  text "2.76mil" at 254.866,199.685 h0.35
  text "Dielectric 1" at 249.502,198.985 h0.35
  text "PP-016" at 252.327,198.985 h0.35
  text "4.60mil" at 254.866,198.985 h0.35
  text "4.4" at 256.952,198.985 h0.35
  text "2" at 248.04,198.285 h0.35
  text "Layer 1" at 249.502,198.285 h0.35
  text "CF-004" at 252.327,198.285 h0.35
  text "2.76mil" at 254.866,198.285 h0.35
  text "Dielectric1" at 249.502,197.585 h0.35
  text "Core-037" at 252.327,197.585 h0.35
  text "21.00mil" at 254.866,197.585 h0.35
  text "4.8" at 256.952,197.585 h0.35
  text "3" at 248.04,196.885 h0.35
  text "Layer 2" at 249.502,196.885 h0.35
  text "CF-004" at 252.327,196.885 h0.35
  text "2.76mil" at 254.866,196.885 h0.35
  text "Dielectric 2" at 249.502,196.185 h0.35
  text "PP-016" at 252.327,196.185 h0.35
  text "4.60mil" at 254.866,196.185 h0.35
  text "4.4" at 256.952,196.185 h0.35
  text "4" at 248.04,195.485 h0.35
  text "Bottom Layer" at 249.502,195.485 h0.35
  text "2.76mil" at 254.866,195.485 h0.35
  text "Bottom Solder" at 249.502,194.785 h0.35
  text "Solder Resist" at 252.327,194.785 h0.35
  text "0.40mil" at 254.866,194.785 h0.35
  text "3.5" at 256.952,194.785 h0.35
  text "Bottom Overlay" at 249.502,194.085 h0.35
  text ".Layer_Name" at 14.656,-21.806 h0.35
M13 Component Bodies Top:
  text ".Layer_Name" at 14.656,-21.806 h0.35
M14 Component Bodies Bottom:
  text ".Layer_Name" at 14.656,-21.806 h0.35
M15 Courtyards Top:
  text ".Layer_Name" at 14.656,-21.806 h0.35
M16 Courtyards Bottom:
  text ".Layer_Name" at 14.656,-21.806 h0.35
Drill Drawing:
  drawing of 176 lines, arcs and shapes, not listed
  text "Symbol" at 134.698,87.734 h0.42
  text "Quantity" at 136.45,87.734 h0.42
  text "Finished Hole Size" at 138.386,87.734 h0.42
  text "Plated" at 142.098,87.734 h0.42
  text "Hole Type" at 143.609,87.734 h0.42
  text "Drill Layer Pair" at 145.796,87.734 h0.42
  text "Hole Tolerance" at 150.006,87.734 h0.42
  text "2" at 136.45,87.011 h0.35
  text "50.00mil (1.270mm)" at 138.386,87.011 h0.35
  text "NPTH" at 142.098,87.011 h0.35
  text "Round" at 143.609,87.011 h0.35
  text "Top Layer - Bottom Layer" at 145.796,87.011 h0.35
  text "4" at 136.45,86.289 h0.35
  text "7.87mil (0.200mm)" at 138.386,86.289 h0.35
  text "PTH" at 142.098,86.289 h0.35
  text "Round" at 143.609,86.289 h0.35
  text "Top Layer - Bottom Layer" at 145.796,86.289 h0.35
  text "1" at 136.45,85.566 h0.35
  text "9.84mil (0.250mm)" at 138.386,85.566 h0.35
  text "PTH" at 142.098,85.566 h0.35
  text "Round" at 143.609,85.566 h0.35
  text "Top Layer - Bottom Layer" at 145.796,85.566 h0.35
  text "D" at 134.416,85.312 h0.32
  text "376" at 136.45,84.843 h0.35
  text "10.00mil (0.254mm)" at 138.386,84.843 h0.35
  text "PTH" at 142.098,84.843 h0.35
  text "Round" at 143.609,84.843 h0.35
  text "Top Layer - Bottom Layer" at 145.796,84.843 h0.35
  text "4" at 136.45,84.121 h0.35
  text "10.24mil (0.260mm)" at 138.386,84.121 h0.35
  text "PTH" at 142.098,84.121 h0.35
  text "Round" at 143.609,84.121 h0.35
  text "Top Layer - Bottom Layer" at 145.796,84.121 h0.35
  text "F" at 134.416,83.867 h0.32
  text "34" at 136.45,83.398 h0.35
  text "11.81mil (0.300mm)" at 138.386,83.398 h0.35
  text "PTH" at 142.098,83.398 h0.35
  text "Round" at 143.609,83.398 h0.35
  text "Top Layer - Bottom Layer" at 145.796,83.398 h0.35
  text "12" at 136.45,82.676 h0.35
  text "12.60mil (0.320mm)" at 138.386,82.676 h0.35
  text "PTH" at 142.098,82.676 h0.35
  text "Round" at 143.609,82.676 h0.35
  text "Top Layer - Bottom Layer" at 145.796,82.676 h0.35
  text "C" at 134.416,82.422 h0.32
  text "3" at 136.45,81.953 h0.35
  text "12.99mil (0.330mm)" at 138.386,81.953 h0.35
  text "PTH" at 142.098,81.953 h0.35
  text "Round" at 143.609,81.953 h0.35
  text "Top Layer - Bottom Layer" at 145.796,81.953 h0.35
  text "B" at 134.416,81.699 h0.32
  text "14" at 136.45,81.231 h0.35
  text "13.78mil (0.350mm)" at 138.386,81.231 h0.35
  text "PTH" at 142.098,81.231 h0.35
  text "Round" at 143.609,81.231 h0.35
  text "Top Layer - Bottom Layer" at 145.796,81.231 h0.35
  text "A" at 134.416,80.977 h0.32
  text "4" at 136.45,80.508 h0.35
  text "17.72mil (0.450mm)" at 138.386,80.508 h0.35
  text "PTH" at 142.098,80.508 h0.35
  text "Round" at 143.609,80.508 h0.35
  text "Top Layer - Bottom Layer" at 145.796,80.508 h0.35
  text "12" at 136.45,79.785 h0.35
  text "27.56mil (0.700mm)" at 138.386,79.785 h0.35
  text "PTH" at 142.098,79.785 h0.35
  text "Round" at 143.609,79.785 h0.35
  text "Top Layer - Bottom Layer" at 145.796,79.785 h0.35
  text "E" at 134.416,79.531 h0.32
  text "2" at 136.45,79.063 h0.35
  text "33.07mil (0.840mm)" at 138.386,79.063 h0.35
  text "PTH" at 142.098,79.063 h0.35
  text "Round" at 143.609,79.063 h0.35
  text "Top Layer - Bottom Layer" at 145.796,79.063 h0.35
  text "4" at 136.45,78.34 h0.35
  text "37.40mil (0.950mm)" at 138.386,78.34 h0.35
  text "PTH" at 142.098,78.34 h0.35
  text "Round" at 143.609,78.34 h0.35
  text "Top Layer - Bottom Layer" at 145.796,78.34 h0.35
  text "4" at 136.45,77.618 h0.35
  text "39.37mil (1.000mm)" at 138.386,77.618 h0.35
  text "PTH" at 142.098,77.618 h0.35
  text "Round" at 143.609,77.618 h0.35
  text "Top Layer - Bottom Layer" at 145.796,77.618 h0.35
  text "10" at 136.45,76.895 h0.35
  text "40.16mil (1.020mm)" at 138.386,76.895 h0.35
  text "PTH" at 142.098,76.895 h0.35
  text "Round" at 143.609,76.895 h0.35
  text "Top Layer - Bottom Layer" at 145.796,76.895 h0.35
  text "12" at 136.45,76.173 h0.35
  text "75.00mil (1.905mm)" at 138.386,76.173 h0.35
  text "PTH" at 142.098,76.173 h0.35
  text "Round" at 143.609,76.173 h0.35
  text "Top Layer - Bottom Layer" at 145.796,76.173 h0.35
  text "2" at 136.45,75.45 h0.35
  text "96.46mil (2.450mm)" at 138.386,75.45 h0.35
  text "PTH" at 142.098,75.45 h0.35
  text "Round" at 143.609,75.45 h0.35
  text "Top Layer - Bottom Layer" at 145.796,75.45 h0.35
  text "4" at 136.45,74.727 h0.35
  text "125.98mil (3.200mm)" at 138.386,74.727 h0.35
  text "PTH" at 142.098,74.727 h0.35
  text "Round" at 143.609,74.727 h0.35
  text "Top Layer - Bottom Layer" at 145.796,74.727 h0.35
  text "4" at 136.45,74.005 h0.35
  text "137.79mil (3.500mm)" at 138.386,74.005 h0.35
  text "PTH" at 142.098,74.005 h0.35
  text "Round" at 143.609,74.005 h0.35
  text "Top Layer - Bottom Layer" at 145.796,74.005 h0.35
  text "2" at 136.45,73.282 h0.35
  text "124.02mil (3.150mm)" at 138.386,73.282 h0.35
  text "PTH" at 142.098,73.282 h0.35
  text "Slot" at 143.609,73.282 h0.35
  text "Top Layer - Bottom Layer" at 145.796,73.282 h0.35
  text "510 Total" at 136.45,72.56 h0.35
  text "Slot definitions :" at 134.698,72.054 h0.35
  text "Routed Path Length" at 137.318,72.054 h0.35
  text "= Calculated from tool start centre position to tool end centre position." at 140.455,72.054 h0.35
  text "Hole Length" at 137.318,71.765 h0.35
  text "= Routed Path Length + Tool Size = Slot length as defined in the PCB layout" at 139.293,71.765 h0.35
  text ".Layer_Name" at 14.656,-21.806 h0.35
M17 Embedded Cavity:
  text ".Layer_Name" at 14.656,-21.806 h0.35
M18 Embedded Assembly:
  text ".Layer_Name" at 14.656,-21.806 h0.35
M19 Embedded Keepout:
  text ".Layer_Name" at 14.656,-21.806 h0.35

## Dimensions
0,-10.16 to 25.4,-10.16 on M2 Board Dimensions
0,0 to 0,87.63 on M2 Board Dimensions
0,0 to 125.73,0 on M2 Board Dimensions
